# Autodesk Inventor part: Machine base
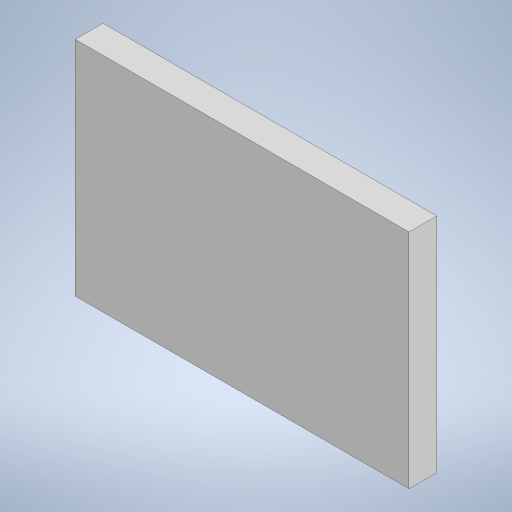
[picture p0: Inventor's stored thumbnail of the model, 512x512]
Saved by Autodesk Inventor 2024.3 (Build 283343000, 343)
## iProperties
Created: 2024-12
Part Number: Machine base
Material: Generic
Document SubType Name: Modeling
Designer: ruhr
Density: 1 g/cm^3
Appearance: Default
Author: ruhr
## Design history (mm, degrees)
sketch "Sketch1"
  geometry: L1 (-120, 80)-(120, 80); L2 (120, 80)-(120, -80); L3 (120, -80)-(-120, -80); L4 (-120, -80)-(-120, 80); L5 (-120, 80)-(120, -80); L6 (120, 80)-(-120, -80); 1 further point
  constraints: 12 end point, 2 midpoint, 2 parallel, 1 horizontal, 1 perpendicular
  dimensions: "d0" = 240 distance of L2.end L3.end; "d1" = 160 distance of L1.end L2.end
extrude "Extrusion1" new body sketch "Sketch1" distance "d2" = 20; taper "d3" = 0 deg
body "Solid1"
